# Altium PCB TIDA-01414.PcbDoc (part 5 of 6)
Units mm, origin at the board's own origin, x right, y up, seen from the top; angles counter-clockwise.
Board outline 400 x 135 mm, 4 copper layers (Top Copper, Copper Layer 2, Copper Layer 3, Bottom Copper), stack 1.567 mm thick; 835 components, 519 nets, 2420 pads, 2045 vias.
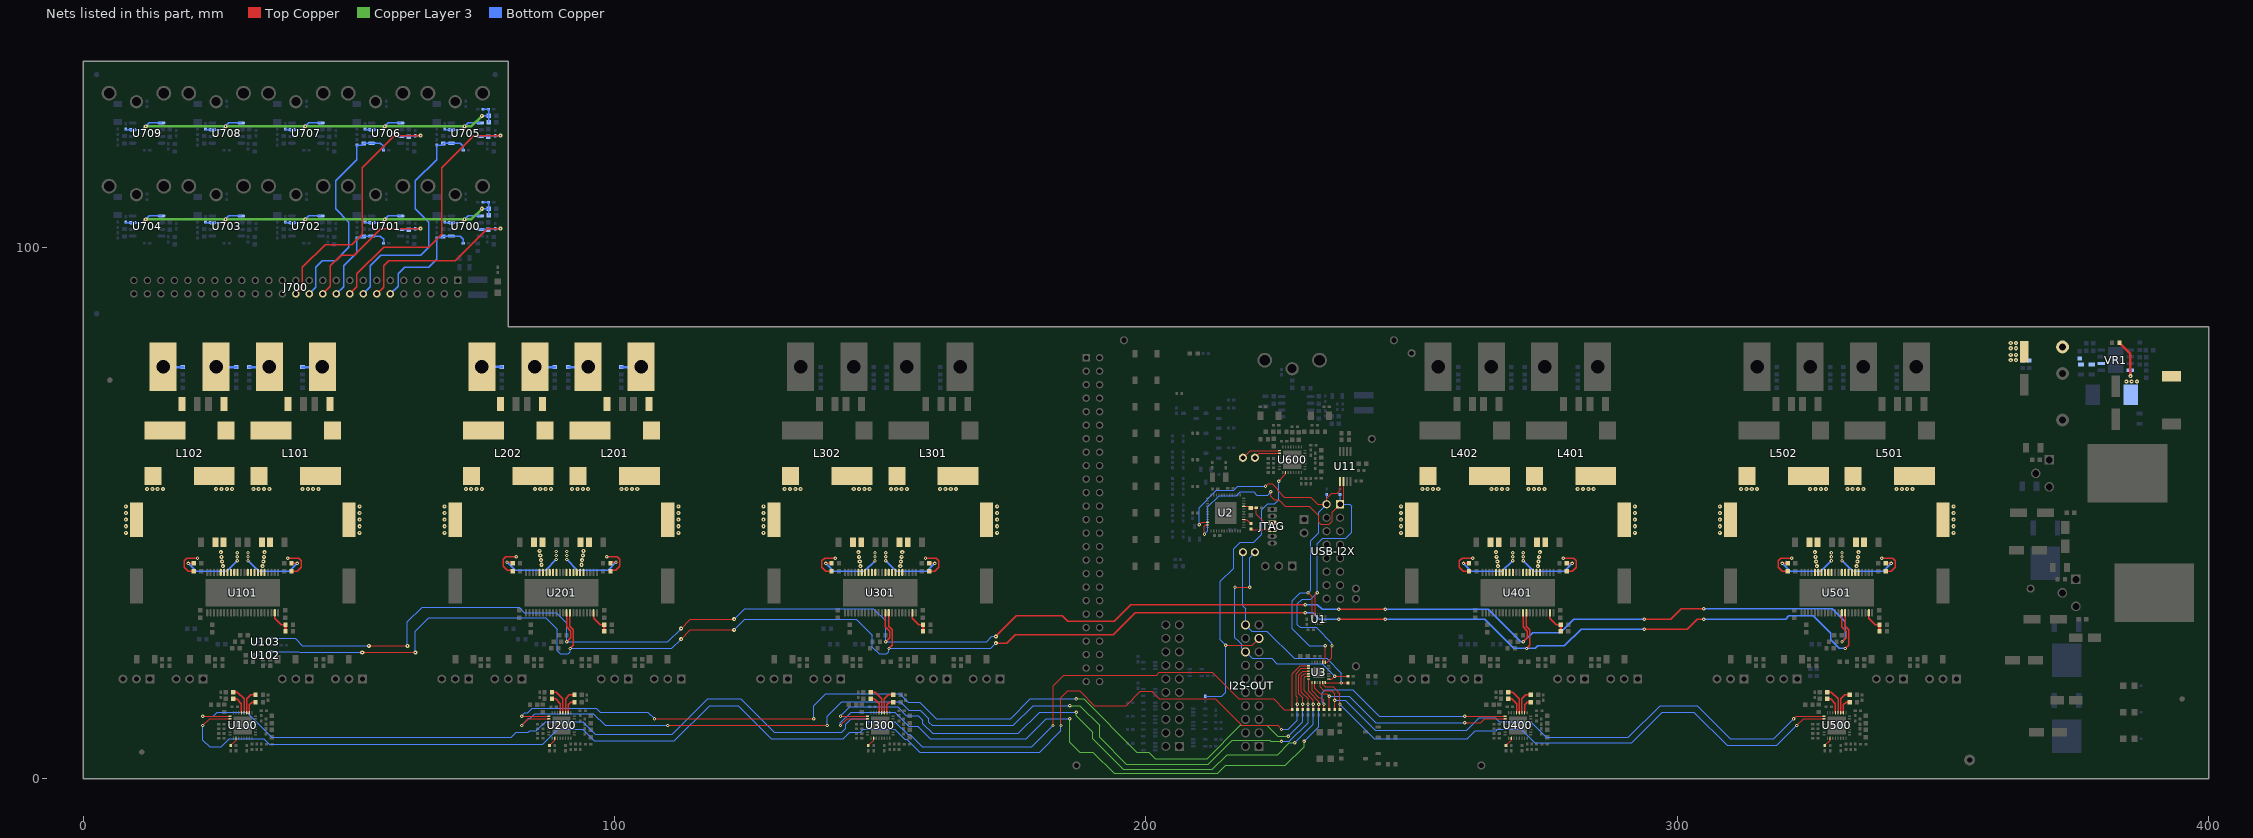
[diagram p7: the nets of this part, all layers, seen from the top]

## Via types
v1: diameter 0.635, hole 0.254, Top Copper to Bottom Copper, tented both sides, 1429 vias
v2: diameter 0.762, hole 0.254, Top Copper to Bottom Copper, tented both sides, 311 vias
v3: diameter 0.5, hole 0.2, Top Copper to Bottom Copper, 150 vias
v4: diameter 0.5, hole 0.2, Top Copper to Bottom Copper, tented both sides, 124 vias
v5: diameter 0.508, hole 0.254, Top Copper to Bottom Copper, tented both sides, 21 vias
v6: diameter 6.5, hole 4.5, Top Copper to Bottom Copper, tented both sides, 9 vias
v7: diameter 0.889, hole 0.254, Top Copper to Bottom Copper, tented both sides, 1 vias

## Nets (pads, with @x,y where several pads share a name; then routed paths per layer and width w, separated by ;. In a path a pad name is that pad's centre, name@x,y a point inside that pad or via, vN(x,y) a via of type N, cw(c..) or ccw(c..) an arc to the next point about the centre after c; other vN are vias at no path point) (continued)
OSC-IOM: U102.4 U201.14 U301.14 U401.14 U501.14 | length 355
  Top Copper w0.2: v2(52.5,23.75) v2(62.5,23.75) ; v2(112.5,26.25) 114.25,28 v2(122.5,28)
  Top Copper w0.25: U201.14@91.588,31.3 91.588,28.663 92.25,28 92.25,25.125 v1(91.625,24.5) ; U301.14@151.587,31.3 151.587,28.663 152.25,28 152.25,25.125 v1(151.625,24.5) ; v2(171.75,25.5) 173.75,25.5 175.375,27.125 193.875,27.125 198,31.25 v1(230,31.25) ; v1(236.25,30) v1(245,30) ; U401.14@271.588,31.3 271.588,28.663 272.25,28 272.25,25.125 v1(271.625,24.5) ; v1(293.75,28.125) 301.875,28.125 303.75,30 v1(305,30) ; U501.14@331.588,31.2 331.588,28.663 332.25,28 332.25,25.125 v1(331.625,24.5)
  Bottom Copper w0.2: U102.4@35.375,23.9 40.65,23.9 40.8,23.75 v2(52.5,23.75) ; v2(62.5,23.75) 62.5,27.75 65,30.25 87,30.25 89.179,28.071 89.179,24.071 89.75,23.5 91.25,23.5 91.625,23.875 v1(91.625,24.5) 110.75,24.5 v2(112.5,26.25) ; v2(122.5,28) 124.5,30 145.5,30 148.5,27 148.5,24.75 149.75,23.5 151.25,23.5 151.625,23.875 v1(151.625,24.5) 170.75,24.5 v2(171.75,25.5)
  Bottom Copper w0.25: v1(230,31.25) 231.375,31.25 232.625,30 v1(236.25,30) ; v1(245,30) 263.75,30 269.25,24.5 v1(271.625,24.5) 273.25,24.5 273.75,25 278.75,25 281.875,28.125 v1(293.75,28.125) ; v1(305,30) 320.375,30 321,30.625 325.625,30.625 328.875,27.375 328.875,26.125 330.5,24.5 v1(331.625,24.5)
OSC-IOP: U103.4 U201.13 U301.13 U401.13 U501.13 | length 353.6
  Top Copper w0.2: v2(53.75,25) v2(61,25) ; v2(112.5,28.25) 114.25,30 v2(122.5,30)
  Top Copper w0.25: U201.13@90.953,31.3 U201.13@90.953,31.2 90.953,28.548 91.75,27.75 91.75,26.5 v1(91,25.75) ; U301.13@150.952,31.3 U301.13@150.952,31.2 150.952,28.548 151.75,27.75 151.75,26.5 v1(151,25.75) ; v2(171.75,26.75) 175.625,30.625 184.25,30.625 185.25,29.625 194,29.625 197.125,32.75 v1(230,32.75) ; v1(236.25,31.875) v1(245,31.875) ; U401.13@270.953,31.3 U401.13@270.953,31.2 270.953,28.548 271.75,27.75 271.75,26.5 v1(271,25.75) ; v1(293.75,30) 298.75,30 300.75,32 v1(305,32) ; U501.13@330.953,31.2 330.953,28.548 331.75,27.75 331.75,26.5 v1(331,25.75)
  Bottom Copper w0.2: U103.4@35.375,26.4 39.85,26.4 41.25,25 v2(53.75,25) ; v2(61,25) 61,29.5 63.75,32.25 82,32.25 83,31.25 89,31.25 91,29.25 v1(91,25.75) 110,25.75 v2(112.5,28.25) ; v2(122.5,30) 124.5,32 148.702,32 151,29.702 v1(151,25.75) 170,25.75 171,26.75 v2(171.75,26.75)
  Bottom Copper w0.25: v1(230,32.75) 232.25,32.75 233.125,31.875 v1(236.25,31.875) ; v1(245,31.875) 264.375,31.875 270.5,25.75 v1(271,25.75) 272.75,27.5 278,27.5 280.5,30 v1(293.75,30) ; v1(305,32) 329.125,32 331.625,29.5 331.625,26.375 v1(331,25.75)
OUT1A: C120.1 L101.1 U101.27 U101.28 | length 6.4
  Top Copper w0.25: v1(38.5,41.5) 40.5,41.5 41,41 41,39.75 ; C120.1@39.2,39 40.25,39 41,39.75 ; 40.75,39.5 41,39.75
  other v2: 33.75,40 33.875,40.875 34,41.75 34.125,42.625 41.25,54.5 42.25,54.5 43.25,54.5 44.25,54.5
OUT1B: C123.1 L101.4 U101.32 | length 11.7
  Top Copper w0.25: C123.1@39.2,40.5 v1(40.25,40.5)
  Bottom Copper w0.25: v1(31,41) 33,39 38.75,39 v1(40.25,40.5)
  other v1: 31,41.75 31,42.5
  other v2: 32,54.5 33,54.5 34,54.5 35,54.5
OUT1C: C138.1 L102.1 U101.35 | length 11.7
  Top Copper w0.25: v1(19.75,40.5) C138.1@20.8,40.5
  Bottom Copper w0.25: v1(19.75,40.5) 21.25,39 27,39 v1(29,41)
  other v1: 29,41.75 29,42.5
  other v2: 25,54.5 26,54.5 27,54.5 28,54.5
OUT1D: C139.1 L102.4 U101.39 U101.40 | length 6.1
  Top Copper w0.25: C139.1@20.8,39 19.75,39 19,39.75 19,40.25 19,41 19.5,41.5 v1(21.5,41.5)
  other v2: 26.25,40 26.125,40.875 26,41.75 25.875,42.625 12,54.5 13,54.5 14,54.5 15,54.5
OUT2A: C220.1 L201.1 U201.27 U201.28 | length 6.4
  Top Copper w0.25: v1(98.5,41.75) 100.5,41.75 101,41.25 101,40 ; C220.1@99.2,39.25 100.25,39.25 101,40 ; 100.75,39.75 101,40
  other v2: 93.75,40.25 93.875,41.125 94,42 94.125,42.875 101.25,54.5 102.25,54.5 103.25,54.5 104.25,54.5
OUT2B: C223.1 L201.4 U201.32 | length 11.7
  Top Copper w0.25: C223.1@99.2,40.75 v1(100.25,40.75)
  Bottom Copper w0.25: v1(91,41.25) 93,39.25 98.75,39.25 v1(100.25,40.75)
  other v1: 91,42 91,42.75
  other v2: 92,54.5 93,54.5 94,54.5 95,54.5
OUT2C: C238.1 L202.1 U201.35 | length 11.7
  Top Copper w0.25: v1(79.75,40.75) C238.1@80.8,40.75
  Bottom Copper w0.25: v1(79.75,40.75) 81.25,39.25 87,39.25 v1(89,41.25)
  other v1: 89,42 89,42.75
  other v2: 85,54.5 86,54.5 87,54.5 88,54.5
OUT2D: C239.1 L202.4 U201.39 U201.40 | length 6.1
  Top Copper w0.25: C239.1@80.8,39.25 79.75,39.25 79,40 79,40.5 79,41.25 79.5,41.75 v1(81.5,41.75)
  other v2: 86.25,40.25 86.125,41.125 86,42 85.875,42.875 72,54.5 73,54.5 74,54.5 75,54.5
OUT3A: C320.1 L301.1 U301.27 U301.28 | length 6.4
  Top Copper w0.25: v1(158.5,41.5) 160.5,41.5 161,41 161,39.75 ; C320.1@159.2,39 160.25,39 161,39.75 ; 160.75,39.5 161,39.75
  other v2: 153.75,40 153.875,40.875 154,41.75 154.125,42.625 161.25,54.5 162.25,54.5 163.25,54.5 164.25,54.5
OUT3B: C323.1 L301.4 U301.32 | length 11.7
  Top Copper w0.25: C323.1@159.2,40.5 v1(160.25,40.5)
  Bottom Copper w0.25: v1(151,41) 153,39 158.75,39 v1(160.25,40.5)
  other v1: 151,41.75 151,42.5
  other v2: 152,54.5 153,54.5 154,54.5 155,54.5
OUT3C: C338.1 L302.1 U301.35 | length 11.7
  Top Copper w0.25: v1(139.75,40.5) C338.1@140.8,40.5
  Bottom Copper w0.25: v1(139.75,40.5) 141.25,39 147,39 v1(149,41)
  other v1: 149,41.75 149,42.5
  other v2: 145,54.5 146,54.5 147,54.5 148,54.5
OUT3D: C339.1 L302.4 U301.39 U301.40 | length 6.1
  Top Copper w0.25: C339.1@140.8,39 139.75,39 139,39.75 139,40.25 139,41 139.5,41.5 v1(141.5,41.5)
  other v2: 146.25,40 146.125,40.875 146,41.75 145.875,42.625 132,54.5 133,54.5 134,54.5 135,54.5
OUT4A: C420.1 L401.1 U401.27 U401.28 | length 6.4
  Top Copper w0.25: v1(278.5,41.5) 280.5,41.5 281,41 281,39.75 ; C420.1@279.2,39 280.25,39 281,39.75 ; 280.75,39.5 281,39.75
  other v2: 273.75,40 273.875,40.875 274,41.75 274.125,42.625 281.25,54.5 282.25,54.5 283.25,54.5 284.25,54.5
OUT4B: C423.1 L401.4 U401.32 | length 11.7
  Top Copper w0.25: C423.1@279.2,40.5 v1(280.25,40.5)
  Bottom Copper w0.25: v1(271,41) 273,39 278.75,39 v1(280.25,40.5)
  other v1: 271,41.75 271,42.5
  other v2: 272,54.5 273,54.5 274,54.5 275,54.5
OUT4C: C438.1 L402.1 U401.35 | length 11.7
  Top Copper w0.25: v1(259.75,40.5) C438.1@260.8,40.5
  Bottom Copper w0.25: v1(259.75,40.5) 261.25,39 267,39 v1(269,41)
  other v1: 269,41.75 269,42.5
  other v2: 265,54.5 266,54.5 267,54.5 268,54.5
OUT4D: C439.1 L402.4 U401.39 U401.40 | length 6.1
  Top Copper w0.25: C439.1@260.8,39 259.75,39 259,39.75 259,40.25 259,41 259.5,41.5 v1(261.5,41.5)
  other v2: 266.25,40 266.125,40.875 266,41.75 265.875,42.625 252,54.5 253,54.5 254,54.5 255,54.5
OUT5A: C520.1 L501.1 U501.27 U501.28 | length 6.4
  Top Copper w0.25: v1(338.5,41.5) 340.5,41.5 341,41 341,39.75 ; C520.1@339.2,39 340.25,39 341,39.75 ; 340.75,39.5 341,39.75
  other v2: 333.75,40 333.875,40.875 334,41.75 334.125,42.625 341.25,54.5 342.25,54.5 343.25,54.5 344.25,54.5
OUT5B: C523.1 L501.4 U501.32 | length 11.7
  Top Copper w0.25: C523.1@339.2,40.5 v1(340.25,40.5)
  Bottom Copper w0.25: v1(331,41) 333,39 338.75,39 v1(340.25,40.5)
  other v1: 331,41.75 331,42.5
  other v2: 332,54.5 333,54.5 334,54.5 335,54.5
OUT5C: C538.1 L502.1 U501.35 | length 11.7
  Top Copper w0.25: v1(319.75,40.5) C538.1@320.8,40.5
  Bottom Copper w0.25: v1(319.75,40.5) 321.25,39 327,39 v1(329,41)
  other v1: 329,41.75 329,42.5
  other v2: 325,54.5 326,54.5 327,54.5 328,54.5
OUT5D: C539.1 L502.4 U501.39 U501.40 | length 6.1
  Top Copper w0.25: C539.1@320.8,39 319.75,39 319,39.75 319,40.25 319,41 319.5,41.5 v1(321.5,41.5)
  other v2: 326.25,40 326.125,40.875 326,41.75 325.875,42.625 312,54.5 313,54.5 314,54.5 315,54.5
OUTLN1: R103.1 U100.11 | length 4.6
  Top Copper w0.25: U100.11@30.75,12.4 30.75,15 31.5,15.75 R103.1@32.425,15.75
OUTLN2: R203.1 U200.11 | length 4.6
  Top Copper w0.25: U200.11@90.75,12.4 90.75,15 91.5,15.75 R203.1@92.425,15.75
OUTLN3: R303.1 U300.11 | length 4.6
  Top Copper w0.25: U300.11@150.75,12.4 150.75,15 151.5,15.75 R303.1@152.425,15.75
OUTLN4: R403.1 U400.11 | length 4.6
  Top Copper w0.25: U400.11@270.75,12.4 270.75,15 271.5,15.75 R403.1@272.425,15.75
OUTLN5: R503.1 U500.11 | length 4.6
  Top Copper w0.25: U500.11@330.75,12.4 330.75,15 331.5,15.75 R503.1@332.425,15.75
OUTLP1: R101.1 U100.10 | length 2.9
  Top Copper w0.25: U100.10@31.25,12.4 31.25,13.875 31.75,14.375 R101.1@32.425,14.375
OUTLP2: R201.1 U200.10 | length 2.9
  Top Copper w0.25: U200.10@91.25,12.4 91.25,13.875 91.75,14.375 R201.1@92.425,14.375
OUTLP3: R301.1 U300.10 | length 2.9
  Top Copper w0.25: U300.10@151.25,12.4 151.25,13.875 151.75,14.375 R301.1@152.425,14.375
OUTLP4: R401.1 U400.10 | length 2.9
  Top Copper w0.25: U400.10@271.25,12.4 271.25,13.875 271.75,14.375 R401.1@272.425,14.375
OUTLP5: R501.1 U500.10 | length 2.9
  Top Copper w0.25: U500.10@331.25,12.4 331.25,13.875 331.75,14.375 R501.1@332.425,14.375
OUTRN1: R105.1 U100.12 | length 5.2
  Top Copper w0.25: R105.1@28.2,16.25 29,16.25 30.25,15 U100.12@30.25,12.4
OUTRN2: R205.1 U200.12 | length 5.2
  Top Copper w0.25: R205.1@88.2,16.25 89,16.25 90.25,15 U200.12@90.25,12.4
OUTRN3: R305.1 U300.12 | length 5.2
  Top Copper w0.25: R305.1@148.2,16.25 149,16.25 150.25,15 U300.12@150.25,12.4
OUTRN4: R405.1 U400.12 | length 5.2
  Top Copper w0.25: R405.1@268.2,16.25 269,16.25 270.25,15 U400.12@270.25,12.4
OUTRN5: R505.1 U500.12 | length 5.2
  Top Copper w0.25: R505.1@328.2,16.25 329,16.25 330.25,15 U500.12@330.25,12.4
OUTRP1: R107.1 U100.13 | length 3.6
  Top Copper w0.25: R107.1@28.2,15 28.875,15 29.75,14.125 U100.13@29.75,12.4
OUTRP2: R207.1 U200.13 | length 3.6
  Top Copper w0.25: R207.1@88.2,15 88.875,15 89.75,14.125 U200.13@89.75,12.4
OUTRP3: R307.1 U300.13 | length 3.6
  Top Copper w0.25: R307.1@148.2,15 148.875,15 149.75,14.125 U300.13@149.75,12.4
OUTRP4: R407.1 U400.13 | length 3.6
  Top Copper w0.25: R407.1@268.2,15 268.875,15 269.75,14.125 U400.13@269.75,12.4
OUTRP5: R507.1 U500.13 | length 3.6
  Top Copper w0.25: R507.1@328.2,15 328.875,15 329.75,14.125 U500.13@329.75,12.4
PVDD: C5.1 C6.2 C8.1 C9.1 C10.1 C100.1 C102.2 C103.2 C111.1 C113.2 C114.2 C200.1 C202.2 C203.2 C211.1 C213.2 C214.2 C300.1 C302.2 C303.2 C311.1 C313.2 C314.2 C400.1 C402.2 C403.2 C411.1 C413.2 C414.2 C500.1 C502.2 C503.2 C511.1 C513.2 C514.2 PWR-IN.1 R35.2 U101.29 U101.30 U101.31 U101.36 U101.37 U101.38 U201.29 U201.30 U201.31 U201.36 U201.37 U201.38 U301.29 U301.30 U301.31 U301.36 U301.37 U301.38 U401.29 U401.30 U401.31 U401.36 U401.37 U401.38 U501.29 U501.30 U501.31 U501.36 U501.37 U501.38 VR1.2
  other v2: 8,46.25 52,46.25 68,46.25 112,46.25 128,46.25 172,46.25 248,46.25 292,46.25 308,46.25 352,46.25 8,47.5 52,47.5 68,47.5 112,47.5 128,47.5 172,47.5 248,47.5 292,47.5 308,47.5 352,47.5 8,48.75 52,48.75 68,48.75 112,48.75 128,48.75 172,48.75 248,48.75 292,48.75 308,48.75 352,48.75 8,50 52,50 68,50 112,50 128,50 172,50 248,50 292,50 308,50 352,50 8,51.25 52,51.25 68,51.25 112,51.25 128,51.25 172,51.25 248,51.25 292,51.25 308,51.25 352,51.25 362.75,78.75 363.75,78.75 362.75,79.75 363.75,79.75 362.75,81 363.75,81 362.75,82 363.75,82
SBWTCK: R43.1 U2.40 | length 1.7
  Top Copper w0.2: U2.40@218.4,48.75 219,48.75 R43.1@219.75,48
SBWTDIO: C52.2 JTAG.3 R41.1 U2.45 | length 7.5
  Top Copper w0.2: U2.45@218.4,51.25 219.45,51.25 C52.2@219.75,50.95 C52.2@219.8,51 ; C52.2@219.75,51 C52.2@219.8,51 ; JTAG.3@223.75,48.135 222.365,48.135 220.75,49.75 R41.1@220.75,51 C52.2@219.8,51
SCK1: R81.1 U100.26 | length 1.8
  Top Copper w0.2: R81.1@27.75,6.25 28.75,7.25 U100.26@28.75,7.6
SCK2: R82.1 U200.26 | length 1.8
  Top Copper w0.2: R82.1@87.75,6.25 88.75,7.25 U200.26@88.75,7.6
SCK3: R83.1 U300.26 | length 1.8
  Top Copper w0.2: R83.1@147.75,6.25 148.75,7.25 U300.26@148.75,7.6
SCK4: R84.1 U400.26 | length 1.8
  Top Copper w0.2: R84.1@267.75,6.25 268.75,7.25 U400.26@268.75,7.6
SCK5: R85.1 U500.26 | length 1.8
  Top Copper w0.2: R85.1@327.75,6.25 328.75,7.25 U500.26@328.75,7.6
SCK6: I2S-OUT.17 R86.1 U600.26 | length 60.1
  Top Copper w0.2: v1(215,25.125) 220.005,25.125 I2S-OUT.17@221.27,26.39 ; v1(225,56) 226.25,57.25 U600.26@226.25,57.6
  Bottom Copper w0.2: R86.1@211.125,15.5 214.25,15.5 215,16.25 v1(215,25.125) 214,26.125 214,37.125 216.5,39.625 216.5,43.25 217.75,44.5 220.25,44.5 221.75,46 221.75,50.625 222.875,51.75 224.25,51.75 225,52.5 v1(225,56)
SCL: R12.2 U1.12 U2.23 U3.19 U11.6 USB-I2X.1 | length 96.3
  Top Copper w0.2: v1(211,46) 211,47.5 211.25,47.75 U2.23@211.6,47.75 ; v1(223.5,54) 223.5,53.125 224.125,52.5 225,52.5 225.25,52.25 226.25,51.25 230.75,51.25 232.5,49.5 232.5,48.25 232.875,47.875 234.5,47.875 235.055,48.43 235.055,50.175 USB-I2X.1@236.52,51.64 USB-I2X.1@236.75,51.64 ; U1.12@231.9,30.8 231.9,34.65 v1(232.25,35) ; U3.19@233.75,21.9 234.15,21.9 235,22.75 v1(235,25) ; USB-I2X.1@236.75,51.5 237.175,51.925 U11.6@237.175,55.9
  Bottom Copper w0.2: v1(211,46) 211.625,46.625 211.625,51.125 213.75,53.25 217,53.25 217.75,54 220.25,54 220.875,53.375 222.875,53.375 v1(223.5,54) ; v1(235,25) 235,25.5 232,28.5 229,28.5 228.5,29 228.5,32.875 229.375,33.75 231,33.75 v1(232.25,35) 232.25,44.25 233.25,45.25 237.625,45.25 238.75,46.375 238.75,51.25 238.36,51.64 USB-I2X.1@236.52,51.64 236.52,53.48 R12.2@236.5,53.5
SCL1: R15.1 U3.2 U100.18 | length 252.8
  Top Copper w0.2: v1(22.5,10) 23.75,11.25 U100.18@27.6,11.25 ; v1(184,10) 184,15.25 185.25,16.5 187.5,16.5 190.25,13.75 196.25,13.75 198.937,16.437 201.063,16.437 202.5,15 213,15 218,10 224.75,10 v1(225.5,9.25) ; R15.1@228.5,13 v1(228.5,14) 228.5,15.25 228.25,15.5 228.25,19.75 229.25,20.75 U3.2@230.6,20.75
  Bottom Copper w0.2: v1(22.5,10) 22.5,7.25 23.75,6 26,6 27.5,7.5 34,7.5 35,6.5 86.5,6.5 89.25,9.25 94,9.25 96.125,7.125 111.25,7.125 117.875,13.75 123.25,13.75 129.5,7.5 143,7.5 144.25,8.75 146.25,8.75 146.75,9.25 152.75,9.25 154.625,7.375 155,7.375 157.375,5 180,5 184,9 v1(184,10) ; v1(225.5,9.25) 226.75,9.25 228.5,11 v1(228.5,14)
SCL2: R11.1 U3.4 U200.18 | length 183.3
  Top Copper w0.2: v1(82.5,10) 83.75,11.25 U200.18@87.6,11.25 ; v1(110,10) v1(140,10) ; R11.1@230.5,13 v1(230.5,14) 230.5,15 229.25,16.25 229.25,19.25 229.75,19.75 U3.4@230.6,19.75
  Copper Layer 3 w0.2: v1(185.625,13.75) 187.5,13.75 191.25,10 191.25,7.75 196.25,2.75 211.75,2.75 216.25,7.25 223.25,7.25 223.5,7 v1(225.5,7)
  Bottom Copper w0.2: v1(82.5,10) 83.875,11.375 84.125,11.375 85,12.25 96,12.25 98.25,10 v1(110,10) ; v1(140,10) 140,11.75 142.75,14.5 153.75,14.5 155.375,12.875 157.5,12.875 159.125,11.25 159.125,10.625 159.75,10 175,10 178.75,13.75 v1(185.625,13.75) ; v1(225.5,7) 227,7 230.5,10.5 v1(230.5,14)
SCL3: R9.1 U3.6 U300.18 | length 122.4
  Top Copper w0.2: v1(142.5,10) 143.75,11.25 U300.18@147.6,11.25 ; U3.6@230.6,18.75 230.6,16.4 232.5,14.5 v1(232.5,14) R9.1@232.5,13
  Copper Layer 3 w0.2: v1(185.625,11.25) 185.625,6.875 187.5,5 190,5 194,1 213.5,1 215,2.5 226.25,2.5 229.75,6 v1(229.75,7)
  Bottom Copper w0.2: v1(142.5,10) 142.5,10.5 144.5,12.5 152.75,12.5 155.375,9.875 157,9.875 159.375,7.5 177.5,7.5 181.25,11.25 v1(185.625,11.25) ; v1(229.75,7) 232.5,9.75 v1(232.5,14)
SCL4: R7.1 U3.8 U400.18 | length 42.5
  Top Copper w0.2: U3.8@231.75,18.1 231.75,17 232.75,16 234,16 v1(234.5,15.5) R7.1@234.5,13 ; v1(260,10.5) 263,10.5 263.75,11.25 U400.18@267.6,11.25
  Bottom Copper w0.2: v1(234.5,15.5) 238.25,15.5 243.25,10.5 v1(260,10.5)
SCL5: R5.1 U3.11 U500.18 | length 109.9
  Top Copper w0.2: U3.11@233.25,18.1 233.25,17.75 233.75,17.25 235.25,17.25 236.5,16 v1(236.5,14) R5.1@236.5,13 ; v1(322.5,10) 323.75,11.25 U500.18@327.6,11.25
  Bottom Copper w0.2: v1(236.5,14) 243,7.5 260.5,7.5 262,9 265.875,9 266.125,9.25 270.625,9.25 273.125,6.75 291.375,6.75 297.125,12.5 303.125,12.5 309.375,6.25 318.75,6.25 v1(322.5,10)
SCL6: I2S-OUT.16 J601.1 R3.1 U3.13 | length 45.2
  Top Copper w0.2: v1(216.75,36) v1(219.5,36) ; U3.13@234.4,18.75 235,18.75 v1(235.5,19.25) R3.1@238,19.25
  Bottom Copper w0.2: v1(216.75,36) 216.75,26.5 217.25,26 218,25.25 218,24.58 I2S-OUT.16@218.73,23.85 219.955,22.625 223.625,22.625 224.625,21.625 233.125,21.625 v1(235.5,19.25) ; v1(219.5,36) 219.5,41.61 J601.1@220.5,42.61
SCL7: J601.2 U600.18 | length 5
  Top Copper w0.2: J601.2@220.5,60.39 221.36,61.25 U600.18@225.1,61.25
SDA: R13.2 U1.13 U2.22 U3.20 U11.5 USB-I2X.2 | length 83
  Top Copper w0.2: v1(210,47.75) 210.5,48.25 U2.22@211.6,48.25 ; v1(222.5,55) 223,55.5 223.75,55.5 224.75,54.5 224.75,54.25 226,53 231,53 232.36,51.64 USB-I2X.2@233.98,51.64 233.98,52.73 235,53.75 236,53.75 236.525,54.275 U11.5@236.525,55.9 ; v1(230.5,35) 231.3,34.2 U1.13@231.3,30.6 ; U3.20@233.25,21.9 233.25,22.25 233.75,22.75 v1(233.75,25)
  Bottom Copper w0.2: v1(210,47.75) 210,51 213.25,54.25 216.5,54.25 217.25,55 v1(222.5,55) ; v1(233.75,25) 230.75,25 227.5,28.25 227.5,33.5 229,35 v1(230.5,35) 231,35.5 231,44.75 232.5,46.25 232.5,50.16 USB-I2X.2@233.98,51.64 233.98,53.48 R13.2@234,53.5
SDA1: R16.1 U3.1 U100.17 | length 247.2
  Top Copper w0.2: v1(22.5,11.75) U100.17@27.6,11.75 ; v1(182.5,10) 182.5,17.5 184.5,19.5 202,19.5 202.5,20 212.5,20 217.5,15 224,15 226,13 R16.1@227.5,13 227.5,19.75 229,21.25 U3.1@230.6,21.25
  Bottom Copper w0.2: v1(22.5,11.75) 24.5,11.75 25.25,12.5 30.75,12.5 35.5,7.75 80.5,7.75 81.5,8.75 83.75,8.75 84,9 85.25,9 85.5,9.25 87,10.75 94,10.75 96.375,8.375 110.875,8.375 117.5,15 123.75,15 130,8.75 142.75,8.75 143.5,9.5 143.5,10.25 144.5,11.25 147.25,11.25 147.75,10.75 152.75,10.75 155.125,8.375 155.5,8.375 157.875,6 178.5,6 v1(182.5,10)
SDA2: R14.1 U3.3 U200.17 | length 181.9
  Top Copper w0.2: v1(82.5,11.75) U200.17@87.6,11.75 ; v1(107.5,11.25) v1(137.5,11.25) ; R14.1@229.5,13 v1(229.5,14) 229.5,15.25 228.75,16 228.75,19.5 229.5,20.25 U3.3@230.6,20.25
  Copper Layer 3 w0.2: v1(186.875,15) 188.25,15 198.25,5 200.5,5 201.75,3.75 211.5,3.75 217.75,10 222.75,10 224.75,8 v1(226.75,8)
  Bottom Copper w0.2: v1(82.5,11.75) 83.125,12.375 83.625,12.375 84.5,13.25 96.5,13.25 97.25,12.5 106.25,12.5 v1(107.5,11.25) ; v1(137.5,11.25) 137.5,13.75 139.75,16 153.625,16 155.25,14.375 157.375,14.375 160.5,11.25 174.5,11.25 178.25,15 v1(186.875,15) ; v1(226.75,8) 229.5,10.75 v1(229.5,14)
SDA3: R10.1 U3.5 U300.17 | length 119.4
  Top Copper w0.2: v1(142.5,11.75) U300.17@147.6,11.75 ; U3.5@230.6,19.25 230,19.25 229.75,19 229.75,16.5 231.5,14.75 v1(231.5,14) R10.1@231.5,13
  Copper Layer 3 w0.2: v1(186.875,12.5) 186.875,11.875 190,8.75 190,7.5 195.75,1.75 212.5,1.75 215.25,4.5 224.75,4.5 227,6.75 v1(228,6.75)
  Bottom Copper w0.2: v1(142.5,11.75) 144.25,13.5 153.25,13.5 154.875,11.875 157.125,11.875 158,11 158,10.375 159.875,8.5 176,8.5 180,12.5 v1(186.875,12.5) ; v1(228,6.75) 231.5,10.25 v1(231.5,14)
SDA4: R8.1 U3.7 U400.17 | length 45.4
  Top Copper w0.2: U3.7@231.25,18.1 231.25,16.5 232.5,15.25 233,15.25 233.5,14.75 v1(233.5,14) R8.1@233.5,13 ; v1(260,11.75) U400.17@267.6,11.75
  Bottom Copper w0.2: v1(233.5,14) 233.125,14.375 233.125,16.125 233.75,16.75 238.875,16.75 243.875,11.75 v1(260,11.75)
SDA5: R6.1 U3.10 U500.17 | length 110.9
  Top Copper w0.2: U3.10@232.75,18.1 232.75,17.25 233.5,16.5 235,16.5 235.5,16 v1(235.5,14.75) R6.1@235.5,13 ; v1(321.875,11.25) 322.375,11.75 U500.17@327.6,11.75
  Bottom Copper w0.2: v1(235.5,14.75) 237.5,14.75 243.125,9.125 260.375,9.125 262.75,11.5 265.75,11.5 266.5,10.75 272.375,10.75 275.375,7.75 290.75,7.75 296.75,13.75 303.75,13.75 310,7.5 318.125,7.5 v1(321.875,11.25)
SDA6: I2S-OUT.20 J600.1 R4.1 U3.12 | length 41.9
  Top Copper w0.2: U3.12@233.75,18.1 233.75,18 v1(236.75,18) R4.1@238,18
  Bottom Copper w0.2: J600.1@218.25,42.61 218.25,32.5 218.75,32 218.75,28.95 I2S-OUT.20@218.73,28.93 219.91,27.75 222.75,27.75 227.875,22.625 234,22.625 236.75,19.875 v1(236.75,18)
SDA7: J600.2 U600.17 | length 7.4
  Top Copper w0.2: J600.2@218.25,60.39 219.61,61.75 U600.17@225.1,61.75
SL+: C727.2 J700.12 R700.1 R710.1 U700.1 | length 22.9
  Bottom Copper w0.25: J700.12@57.78,91.23 59.25,92.7 59.25,95 60.5,96.25 65,96.25 66.5,97.75 R700.1@66.5,101.75 67.45,101.75 C727.2@67.75,102.05 67.795,102.095 U700.1@69.275,102.095 70.905,102.095 71.5,101.5 R710.1@71.5,100.75
SL-: C737.2 J700.14 R715.1 U700.7 | length 34.6
  Top Copper w0.25: J700.14@55.24,91.23 56.5,92.49 56.5,96.5 57.5,97.5 70,97.5 76,103.5 v2(78.5,103.5)
  Bottom Copper w0.25: U700.7@74.725,103.365 76.185,103.365 C737.2@76.25,103.3 76.45,103.5 R715.1@77.5,103.5 v2(78.5,103.5)
SR+: C742.2 J700.16 R720.1 R730.1 U705.1 | length 46.3
  Bottom Copper w0.25: J700.16@52.7,91.23 54,92.53 54,96.5 56,98.5 63.5,98.5 65,100 65,104.75 62.5,107.25 62.5,112.5 66.5,116.5 R720.1@66.5,119.25 67.45,119.25 67.795,119.595 70.905,119.595 71.5,119 R730.1@71.5,118.25
SR-: C752.2 J700.18 R735.1 U705.7 | length 53.3
  Top Copper w0.25: J700.18@50.16,91.23 51.5,92.57 51.5,95 56.5,100 65,100 67.5,102.5 67.5,115 73.5,121 v2(78.5,121)
  Bottom Copper w0.25: U705.7@74.725,120.865 76.185,120.865 C752.2@76.25,120.8 76.45,121 v2(78.5,121)
SURROUNDLEFT+: C115.1 C116.1 L101.2 SL+.1 | length 3.8
  Bottom Copper w0.5: C116.1@41.25,77.45 44.95,77.45 SL+.1@45,77.5
SURROUNDLEFT-: C126.1 C127.1 L101.3 SL-.1 | length 3.8
  Bottom Copper w0.5: C127.1@31.25,77.45 34.95,77.45 SL-.1@35,77.5
SURROUNDRIGHT+: C135.1 C136.1 L102.2 SR+.1 | length 3.8
  Bottom Copper w0.5: SR+.1@25,77.5 25.05,77.45 C136.1@28.75,77.45
SURROUNDRIGHT-: C140.1 C141.1 L102.3 SR-.1 | length 3.8
  Bottom Copper w0.5: SR-.1@15,77.5 15.05,77.45 C141.1@18.75,77.45
SW-VR1: C1.2 D12.1 L1.1 VR1.8 | length 8.2
  Top Copper w0.5: C1.2@383.2,82 385.25,79.95 v2(385.25,75.75)
  Bottom Copper w0.5: VR1.8@385.225,76.845 385.25,76.82 v2(385.25,75.75)
  other v2: 384.5,74.75 385.5,74.75 386.5,74.75
TCK: JTAG.4 R43.2 | length 4.1
  Top Copper w0.2: R43.2@219.75,47 219.885,46.865 JTAG.4@223.75,46.865
UML+: C728.2 J700.20 R701.1 R711.1 U701.1 | length 18.3
  Bottom Copper w0.25: J700.20@47.62,91.23 49,92.61 49,96.5 51.5,99 R701.1@51.5,101.75 52.45,101.75 52.795,102.095 U701.1@54.275,102.095 55.905,102.095 56.5,101.5 R711.1@56.5,100.75
UML-: C738.2 J700.22 R716.1 U701.7 | length 29.6
  Top Copper w0.25: J700.22@45.08,91.23 46.5,92.65 46.5,96.5 48.5,98.5 51,98.5 56,103.5 v2(63.5,103.5)
  Bottom Copper w0.25: U701.7@59.725,103.365 61.185,103.365 C738.2@61.25,103.3 61.45,103.5 R716.1@62.5,103.5 v2(63.5,103.5)
UMR+: C743.2 J700.24 R721.1 R731.1 U706.1 | length 41.4
  Bottom Copper w0.25: J700.24@42.54,91.23 43.75,92.44 43.75,96.25 45,97.5 47.5,97.5 50,100 50,104.75 47.5,107.25 47.5,112.5 51.5,116.5 R721.1@51.5,119.25 52.45,119.25 52.795,119.595 55.905,119.595 56.5,119 R731.1@56.5,118.25
UMR-: C753.2 J700.26 R736.1 U706.7 | length 49.2
  Top Copper w0.25: J700.26@40,91.23 41.25,92.48 41.25,96.25 45.5,100.5 50.5,100.5 52.5,102.5 52.5,115 58.5,121 v2(63.5,121)
  Bottom Copper w0.25: U706.7@59.725,120.865 61.185,120.865 C753.2@61.25,120.8 61.45,121 v2(63.5,121)
UPL+: C215.1 C216.1 L201.2 UPL+.1 | length 3.8
  Bottom Copper w0.5: C216.1@101.25,77.45 104.95,77.45 UPL+.1@105,77.5
UPL-: C226.1 C227.1 L201.3 UPL-.1 | length 3.8
  Bottom Copper w0.5: C227.1@91.25,77.45 94.95,77.45 UPL-.1@95,77.5
UPR+: C235.1 C236.1 L202.2 UPR+.1 | length 3.8
  Bottom Copper w0.5: UPR+.1@85,77.5 85.05,77.45 C236.1@88.75,77.45
UPR-: C240.1 C241.1 L202.3 UPR-.1 | length 3.8
  Bottom Copper w0.5: UPR-.1@75,77.5 78.7,77.5 C241.1@78.75,77.45
VDD1: C112.1 L100.2 U101.21 | length 4.8
  Top Copper w0.25: U101.21@36.033,31.3 U101.21@36.033,31.2 36.033,30.218 37.25,29 C112.1@38,29
  Top Copper w0.5: C112.1@38,29 C112.1@38.05,29 L100.2@38.05,27.8
VDD2: C212.1 L200.2 U201.21 | length 4.8
  Top Copper w0.25: U201.21@96.033,31.3 U201.21@96.033,31.2 96.033,30.218 97.25,29 C212.1@98,29
  Top Copper w0.5: C212.1@98,29 C212.1@98.05,29 L200.2@98.05,27.8
VDD3: C312.1 L300.2 U301.21 | length 4.8
  Top Copper w0.25: U301.21@156.032,31.3 U301.21@156.032,31.2 156.032,30.218 157.25,29 C312.1@158,29
  Top Copper w0.5: C312.1@158,29 C312.1@158.05,29 L300.2@158.05,27.8
VDD4: C412.1 L400.2 U401.21 | length 4.8
  Top Copper w0.25: U401.21@276.033,31.3 U401.21@276.033,31.2 276.033,30.218 277.25,29 C412.1@278,29
  Top Copper w0.5: C412.1@278,29 C412.1@278.05,29 L400.2@278.05,27.8
VDD5: C512.1 L500.2 U501.21 | length 4.8
  Top Copper w0.25: U501.21@336.033,31.3 U501.21@336.033,31.2 336.033,30.218 337.25,29 C512.1@338,29
  Top Copper w0.5: C512.1@338,29 C512.1@338.05,29 L500.2@338.05,27.8
VMID1: C713.2 C714.2 C732.2 C733.2 C734.2 C735.2 C736.2 R740.2 R742.1 U700.3 U700.5 U701.3 U701.5 U702.3 U702.5 U703.3 U703.5 U704.3 U704.5 | length 105.4
  Copper Layer 3 w0.5: v2(11.75,105.25) v2(71.75,105.25) 73,105.25 v2(75,107.25)
  Bottom Copper w0.25: C736.2@8,104.75 8.115,104.635 U704.3@9.275,104.635 11.135,104.635 v2(11.75,105.25) 12.405,105.905 U704.5@14.725,105.905 ; C735.2@23,104.75 23.115,104.635 26.135,104.635 v2(26.75,105.25) 27.405,105.905 U703.5@29.725,105.905 ; C734.2@38,104.75 38.115,104.635 U702.3@39.275,104.635 41.135,104.635 v2(41.75,105.25) 42.405,105.905 U702.5@44.725,105.905 ; C733.2@53,104.75 53.115,104.635 U701.3@54.275,104.635 56.135,104.635 v2(56.75,105.25) 57.405,105.905 U701.5@59.725,105.905 ; C732.2@68,104.75 68.115,104.635 U700.3@69.275,104.635 71.135,104.635 v2(71.75,105.25) 72.405,105.905 U700.5@74.725,105.905 ; v2(75,107.25) C713.2@76.25,107.25 ; R740.2@75.25,108.5 R742.1@76.25,108.5 76.3,108.45 C713.2@76.3,107.25 C713.2@76.25,107.25 ; C714.2@76.3,106 76.3,107.2 C713.2@76.25,107.25
VMID2: C715.2 C716.2 C747.2 C748.2 C749.2 C750.2 C751.2 R741.2 R743.1 U705.3 U705.5 U706.3 U706.5 U707.3 U707.5 U708.3 U708.5 U709.3 U709.5 | length 105.3
  Copper Layer 3 w0.5: v2(11.75,122.75) v2(71.75,122.75) 73,122.75 v2(75,124.75)
  Bottom Copper w0.25: C751.2@8,122.25 8.115,122.135 11.135,122.135 v2(11.75,122.75) 12.405,123.405 U709.5@14.725,123.405 ; C750.2@23,122.25 23.115,122.135 26.135,122.135 v2(26.75,122.75) 27.405,123.405 U708.5@29.725,123.405 ; C749.2@38,122.25 38.115,122.135 41.135,122.135 v2(41.75,122.75) 42.405,123.405 U707.5@44.725,123.405 ; C748.2@53,122.25 53.115,122.135 56.135,122.135 v2(56.75,122.75) 57.405,123.405 U706.5@59.725,123.405 ; C747.2@68,122.25 68.115,122.135 71.135,122.135 v2(71.75,122.75) 72.405,123.405 U705.5@74.725,123.405 ; v2(75,124.75) C716.2@76.3,124.75 76.3,125.95 R743.1@76.25,126 R741.2@75.25,126 ; C715.2@76.3,123.5 76.3,124.55 C716.2@76.4,124.65
pads on no net: FID1.1 FID2.1 FID3.1 FID4.1 FID5.1 FID6.1 FID7.1 FID8.1 FID9.1 I2S-IN.16 I2S-IN.18 I2S-IN.20 I2S-OUT.1 I2S-OUT.2 I2S-OUT.4 I2S-OUT.5 I2S-OUT.6 I2S-OUT.8 I2S-OUT.9 I2S-OUT.12 I2S-OUT.14 I2S-OUT.15 I2S-OUT.18 I2S-OUT.19 J2.10 J700.10 JTAG.1 JTAG.6 U1.8 U1.9 U1.10 U1.11 U2.4 U2.5 U2.21 U2.24 U2.25 U2.26 U2.29 U2.30 U2.31 U2.32 U2.33 U2.34 U2.35 U2.36 U2.38 U2.39 U2.41 U2.42 U2.43 U2.44 U3.14 U3.15 U3.16 U3.17 U3.25@231.93,19.43 U3.25@231.93,20.57 U3.25@233.07,19.43 U3.25@233.07,20.57 U100.16 U100.19 U100.20 U100.21 U100.25 U100.29 U100.30 U101.45@30,35 U200.16 U200.19 U200.20 U200.21 U200.25 U200.29 U200.30 U201.45@90,35 U300.16 U300.19 U300.20 U300.21 U300.25 U300.29 U300.30 U301.45@150,35 U400.16 U400.19 U400.20 U400.21 U400.25 U400.29 U400.30 U401.45@270,35 U500.16 U500.19 U500.20 U500.21 U500.25 U500.29 U500.30 U501.45@330,35 U600.10 U600.11 U600.16 U600.19 U600.20 U600.21 U600.25 U600.29 U600.30 USB-I2X.3 USB-I2X.5 USB-I2X.7 USB-I2X.9 USB-I2X.11 USB-I2X.13 USB-I2X.14 USB-I2X.15 USB-I2X.16 VR1.9@382.5,78.75

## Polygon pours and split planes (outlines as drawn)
3.3V-VR6 on Top Copper "3.3V-VR6 Top Copper" (solid, remove dead copper, pour order 597): 370.5,45 370.75,44.75 370.75,44.25 370.75,43.25 369.5,42 366.75,42 366.5,42.25 366.5,44.5 367,45 370.5,45
3.3V-1 on Top Copper "3.3V-1 Top Copper" (solid, remove dead copper, pour order 589): 366,23.25 367,24.25 369.75,24.25 370,24.25 370.25,24 370.25,20.5 370,20.25 367,20.25 366,21.25 366,23.25
3.3V-2 on Top Copper "3.3V-2 Top Copper" (solid, remove dead copper, pour order 585): 373.5,9.75 372,11.25 369.5,11.25 369.25,11 369.25,5.5 369.5,5.25 371,5.25 373.5,7.75
12V-VR3 on Top Copper "12V-VR3 Top Copper" (solid, remove dead copper, pour order 577): 374.75,33.5 372.25,31 370,31 370,29.25 370.25,29 372,29 373.75,27.25 373.75,13.75 377,13.75 377.5,14.25 377.5,15.5 376.25,16.75 376.25,32.75 375.5,33.5
15V on Top Copper "15V Top Copper" (solid, remove dead copper, pour order 555): 394.25,64.5 394.75,65 394.75,68.5 394.25,69 391.75,69 391.25,68.5 391.25,65 391.75,64.5
15V on Top Copper "15V Top Copper" (solid, remove dead copper, pour order 553): 381,69.75 380.5,69.25 380.5,66.25 381.25,65.5 383.75,65.5 384.5,66.25 384.5,69.25 384,69.75
SW-VR1 on Top Copper "SW-VR1 Top Copper" (solid, remove dead copper, pour order 551): 394.75,76.75 390.5,76.75 389,75.25 384.25,75.25 384,75 384,74.5 384.25,74.25 394.25,74.25 394.75,74.75
PVDD on Top Copper "PWR-IN Top Copper" (solid, remove dead copper, pour order 545): 362.5,82.5 373.25,82.5 374,81.75 374,80 372.25,78.25 362.5,78.25 362,78.75 362,82
CENTERTWEETER+ on Top Copper "CenterTweeter+ Top Copper" (solid, remove dead copper, pour order 513): 345.25,63.75 345.25,72 344.5,72.75 342.5,72.75 342.25,73 342.25,82 342.5,82.25 347.5,82.25 348.5,81.25 348.5,63.75 345.25,63.75
CENTERWOOFER+ on Top Copper "CenterWoofer+ Top Copper" (solid, remove dead copper, pour order 512): 325.25,63.75 325.25,72 324.5,72.75 322.5,72.75 322.25,73 322.25,82 322.5,82.25 327.5,82.25 328.5,81.25 328.5,63.75 325.25,63.75
CENTERTWEETER- on Top Copper "CenterTweeter- Top Copper" (solid, remove dead copper, pour order 511): 331.5,63.75 339.25,63.75 339.25,72 337.75,73.5 337.75,82 337.5,82.25 332.5,82.25 332.25,82 332.25,68 331.5,67.25 331.5,63.75
CENTERWOOFER- on Top Copper "CenterWoofer- Top Copper" (solid, remove dead copper, pour order 510): 311.5,63.75 319.25,63.75 319.25,72 317.75,73.5 317.75,82 317.5,82.25 312.5,82.25 312.25,82 312.25,68 311.5,67.25 311.5,63.75
OUT5A on Top Copper "OUT5A Top Copper" (solid, remove dead copper, pour order 509): 348.5,58.75 340.75,58.75 340.75,54.25 341,54 344.5,54 344.75,54.25 344.75,55 345,55.25 348.5,55.25
OUT5B on Top Copper "OUT5B Top Copper" (solid, remove dead copper, pour order 508): 331.5,58.75 334.75,58.75 335.5,58 335.5,54.25 335.25,54 331.75,54 331.5,54.25
OUT5C on Top Copper "OUT5C Top Copper" (solid, remove dead copper, pour order 507): 320.75,58.75 328.5,58.75 328.5,54.25 328.25,54 324.75,54 324.5,54.25 324.5,55 324.25,55.25 320.75,55.25
OUT5D on Top Copper "OUT5D Top Copper" (solid, remove dead copper, pour order 506): 311.5,58.75 314.75,58.75 315.5,58 315.5,54.25 315.25,54 311.75,54 311.5,54.25
OUT5A on Top Copper "OUT5A Top Copper" (solid, remove dead copper, pour order 505): 334.2,38.075 334.35,38.225 334.35,41.35 334.625,41.625 334.625,42.875 334.375,43.125 333.875,43.125 333.5,42.75 333.5,41.375 333.275,41.15 333.275,38.225 333.425,38.075
OUT5B on Top Copper "OUT5B Top Copper" (solid, remove dead copper, pour order 504): 331.175,38.225 331.025,38.075 330.875,38.075 330.75,38.2 330.75,39.9 330.65,40 330.65,42.625 330.875,42.85 331.125,42.85 331.35,42.625 331.35,40.075 331.175,39.9
OUT5C on Top Copper "OUT5C Top Copper" (solid, remove dead copper, pour order 503): 328.825,38.225 328.975,38.075 329.125,38.075 329.25,38.2 329.25,39.9 329.35,40 329.35,42.625 329.125,42.85 328.875,42.85 328.65,42.625 328.65,40.075 328.825,39.9
OUT5D on Top Copper "OUT5D Top Copper" (solid, remove dead copper, pour order 502): 325.8,38.075 325.65,38.225 325.65,41.35 325.375,41.625 325.375,42.875 325.625,43.125 326.125,43.125 326.5,42.75 326.5,41.375 326.725,41.15 326.725,38.225 326.575,38.075
PVDD on Top Copper "PVDD5a Top Copper" (solid, remove dead copper, pour order 501): 23 vertices, not listed, extent 307.5,38.075 328.625,52
PVDD on Top Copper "PVDD5b Top Copper" (solid, remove dead copper, pour order 500): 23 vertices, not listed, extent 331.375,38.075 352.5,52
FRONTLEFTTWEETER+ on Top Copper "FronLeftTweeter+ Top Copper" (solid, remove dead copper, pour order 495): 285.25,63.75 285.25,72 284.5,72.75 282.5,72.75 282.25,73 282.25,82 282.5,82.25 287.5,82.25 288.5,81.25 288.5,63.75 285.25,63.75
FRONTLEFTWOOFER+ on Top Copper "FronLeftWoofer+ Top Copper" (solid, remove dead copper, pour order 494): 265.25,63.75 265.25,72 264.5,72.75 262.5,72.75 262.25,73 262.25,82 262.5,82.25 267.5,82.25 268.5,81.25 268.5,63.75 265.25,63.75
FRONTLEFTTWEETER- on Top Copper "FronLeftTweeter- Top Copper" (solid, remove dead copper, pour order 493): 271.5,63.75 279.25,63.75 279.25,72 277.75,73.5 277.75,82 277.5,82.25 272.5,82.25 272.25,82 272.25,68 271.5,67.25 271.5,63.75
FRONTLEFTWOOFER- on Top Copper "FronLeftWoofer- Top Copper" (solid, remove dead copper, pour order 492): 251.5,63.75 259.25,63.75 259.25,72 257.75,73.5 257.75,82 257.5,82.25 252.5,82.25 252.25,82 252.25,68 251.5,67.25 251.5,63.75
OUT4A on Top Copper "OUT4A Top Copper" (solid, remove dead copper, pour order 491): 288.5,58.75 280.75,58.75 280.75,54.25 281,54 284.5,54 284.75,54.25 284.75,55 285,55.25 288.5,55.25
OUT4B on Top Copper "OUT4B Top Copper" (solid, remove dead copper, pour order 490): 271.5,58.75 274.75,58.75 275.5,58 275.5,54.25 275.25,54 271.75,54 271.5,54.25
OUT4C on Top Copper "OUT4C Top Copper" (solid, remove dead copper, pour order 489): 260.75,58.75 268.5,58.75 268.5,54.25 268.25,54 264.75,54 264.5,54.25 264.5,55 264.25,55.25 260.75,55.25
OUT4D on Top Copper "OUT4D Top Copper" (solid, remove dead copper, pour order 488): 251.5,58.75 254.75,58.75 255.5,58 255.5,54.25 255.25,54 251.75,54 251.5,54.25
OUT4A on Top Copper "OUT4A Top Copper" (solid, remove dead copper, pour order 487): 274.2,38.075 274.35,38.225 274.35,41.35 274.625,41.625 274.625,42.875 274.375,43.125 273.875,43.125 273.5,42.75 273.5,41.375 273.275,41.15 273.275,38.225 273.425,38.075
OUT4B on Top Copper "OUT4B Top Copper" (solid, remove dead copper, pour order 486): 271.175,38.225 271.025,38.075 270.875,38.075 270.75,38.2 270.75,39.9 270.65,40 270.65,42.625 270.875,42.85 271.125,42.85 271.35,42.625 271.35,40.075 271.175,39.9
OUT4C on Top Copper "OUT4C Top Copper" (solid, remove dead copper, pour order 485): 268.825,38.225 268.975,38.075 269.125,38.075 269.25,38.2 269.25,39.9 269.35,40 269.35,42.625 269.125,42.85 268.875,42.85 268.65,42.625 268.65,40.075 268.825,39.9
OUT4D on Top Copper "OUT4D Top Copper" (solid, remove dead copper, pour order 484): 265.8,38.075 265.65,38.225 265.65,41.35 265.375,41.625 265.375,42.875 265.625,43.125 266.125,43.125 266.5,42.75 266.5,41.375 266.725,41.15 266.725,38.225 266.575,38.075
PVDD on Top Copper "PVDD4a Top Copper" (solid, remove dead copper, pour order 483): 23 vertices, not listed, extent 247.5,38.075 268.625,52
PVDD on Top Copper "PVDD4b Top Copper" (solid, remove dead copper, pour order 482): 23 vertices, not listed, extent 271.375,38.075 292.5,52
FRONTRIGHTTWEETER+ on Top Copper "FrontRightTweeter+ Top Copper" (solid, remove dead copper, pour order 481): 165.25,63.75 165.25,72 164.5,72.75 162.5,72.75 162.25,73 162.25,82 162.5,82.25 167.5,82.25 168.5,81.25 168.5,63.75 165.25,63.75
FRONTRIGHTWOOFER+ on Top Copper "FrontRightWoofer+ Top Copper" (solid, remove dead copper, pour order 480): 145.25,63.75 145.25,72 144.5,72.75 142.5,72.75 142.25,73 142.25,82 142.5,82.25 147.5,82.25 148.5,81.25 148.5,63.75 145.25,63.75
FRONTRIGHTTWEETER- on Top Copper "FrontRightTweeter- Top Copper" (solid, remove dead copper, pour order 479): 151.5,63.75 159.25,63.75 159.25,72 157.75,73.5 157.75,82 157.5,82.25 152.5,82.25 152.25,82 152.25,68 151.5,67.25 151.5,63.75
FRONTRIGHTWOOFER- on Top Copper "FrontRightWoofer- Top Copper" (solid, remove dead copper, pour order 478): 131.5,63.75 139.25,63.75 139.25,72 137.75,73.5 137.75,82 137.5,82.25 132.5,82.25 132.25,82 132.25,68 131.5,67.25 131.5,63.75
OUT3A on Top Copper "OUT3A Top Copper" (solid, remove dead copper, pour order 477): 168.5,58.75 160.75,58.75 160.75,54.25 161,54 164.5,54 164.75,54.25 164.75,55 165,55.25 168.5,55.25
OUT3B on Top Copper "OUT3B Top Copper" (solid, remove dead copper, pour order 476): 151.5,58.75 154.75,58.75 155.5,58 155.5,54.25 155.25,54 151.75,54 151.5,54.25
OUT3C on Top Copper "OUT3C Top Copper" (solid, remove dead copper, pour order 475): 140.75,58.75 148.5,58.75 148.5,54.25 148.25,54 144.75,54 144.5,54.25 144.5,55 144.25,55.25 140.75,55.25
OUT3D on Top Copper "OUT3D Top Copper" (solid, remove dead copper, pour order 474): 131.5,58.75 134.75,58.75 135.5,58 135.5,54.25 135.25,54 131.75,54 131.5,54.25
OUT3A on Top Copper "OUT3A Top Copper" (solid, remove dead copper, pour order 473): 154.2,38.075 154.35,38.225 154.35,41.35 154.625,41.625 154.625,42.875 154.375,43.125 153.875,43.125 153.5,42.75 153.5,41.375 153.275,41.15 153.275,38.225 153.425,38.075
OUT3B on Top Copper "OUT3B Top Copper" (solid, remove dead copper, pour order 472): 151.175,38.225 151.025,38.075 150.875,38.075 150.75,38.2 150.75,39.9 150.65,40 150.65,42.625 150.875,42.85 151.125,42.85 151.35,42.625 151.35,40.075 151.175,39.9
OUT3C on Top Copper "OUT3C Top Copper" (solid, remove dead copper, pour order 471): 148.825,38.225 148.975,38.075 149.125,38.075 149.25,38.2 149.25,39.9 149.35,40 149.35,42.625 149.125,42.85 148.875,42.85 148.65,42.625 148.65,40.075 148.825,39.9
OUT3D on Top Copper "OUT3D Top Copper" (solid, remove dead copper, pour order 470): 145.8,38.075 145.65,38.225 145.65,41.35 145.375,41.625 145.375,42.875 145.625,43.125 146.125,43.125 146.5,42.75 146.5,41.375 146.725,41.15 146.725,38.225 146.575,38.075
PVDD on Top Copper "PVDD3a Top Copper" (solid, remove dead copper, pour order 469): 23 vertices, not listed, extent 127.5,38.075 148.625,52
PVDD on Top Copper "PVDD3b Top Copper" (solid, remove dead copper, pour order 468): 23 vertices, not listed, extent 151.375,38.075 172.5,52
UPL+ on Top Copper "UpL+ Top Copper" (solid, remove dead copper, pour order 467): 105.25,63.75 105.25,72 104.5,72.75 102.5,72.75 102.25,73 102.25,82 102.5,82.25 107.5,82.25 108.5,81.25 108.5,63.75 105.25,63.75
UPR+ on Top Copper "UpR+ Top Copper" (solid, remove dead copper, pour order 466): 85.25,63.75 85.25,72 84.5,72.75 82.5,72.75 82.25,73 82.25,82 82.5,82.25 87.5,82.25 88.5,81.25 88.5,63.75 85.25,63.75
UPL- on Top Copper "UpL- Top Copper" (solid, remove dead copper, pour order 465): 91.5,63.75 99.25,63.75 99.25,72 97.75,73.5 97.75,82 97.5,82.25 92.5,82.25 92.25,82 92.25,68 91.5,67.25 91.5,63.75
UPR- on Top Copper "UpR- Top Copper" (solid, remove dead copper, pour order 464): 71.5,63.75 79.25,63.75 79.25,72 77.75,73.5 77.75,82 77.5,82.25 72.5,82.25 72.25,82 72.25,68 71.5,67.25 71.5,63.75
OUT2A on Top Copper "OUT2A Top Copper" (solid, remove dead copper, pour order 463): 108.5,58.75 100.75,58.75 100.75,54.25 101,54 104.5,54 104.75,54.25 104.75,55 105,55.25 108.5,55.25
OUT2B on Top Copper "OUT2B Top Copper" (solid, remove dead copper, pour order 462): 91.5,58.75 94.75,58.75 95.5,58 95.5,54.25 95.25,54 91.75,54 91.5,54.25
OUT2C on Top Copper "OUT2C Top Copper" (solid, remove dead copper, pour order 461): 80.75,58.75 88.5,58.75 88.5,54.25 88.25,54 84.75,54 84.5,54.25 84.5,55 84.25,55.25 80.75,55.25
OUT2D on Top Copper "OUT2D Top Copper" (solid, remove dead copper, pour order 460): 71.5,58.75 74.75,58.75 75.5,58 75.5,54.25 75.25,54 71.75,54 71.5,54.25
OUT2A on Top Copper "OUT2A Top Copper" (solid, remove dead copper, pour order 459): 94.2,38.075 94.35,38.225 94.35,41.35 94.625,41.625 94.625,42.875 94.375,43.125 93.875,43.125 93.5,42.75 93.5,41.375 93.275,41.15 93.275,38.225 93.425,38.075
OUT2B on Top Copper "OUT2B Top Copper" (solid, remove dead copper, pour order 458): 91.175,38.225 91.025,38.075 90.875,38.075 90.75,38.2 90.75,39.9 90.65,40 90.65,42.625 90.875,42.85 91.125,42.85 91.35,42.625 91.35,40.075 91.175,39.9
OUT2C on Top Copper "OUT2C Top Copper" (solid, remove dead copper, pour order 457): 88.825,38.225 88.975,38.075 89.125,38.075 89.25,38.2 89.25,39.9 89.35,40 89.35,42.625 89.125,42.85 88.875,42.85 88.65,42.625 88.65,40.075 88.825,39.9
OUT2D on Top Copper "OUT2D Top Copper" (solid, remove dead copper, pour order 456): 85.8,38.075 85.65,38.225 85.65,41.35 85.375,41.625 85.375,42.875 85.625,43.125 86.125,43.125 86.5,42.75 86.5,41.375 86.725,41.15 86.725,38.225 86.575,38.075
PVDD on Top Copper "PVDD2a Top Copper" (solid, remove dead copper, pour order 455): 23 vertices, not listed, extent 67.5,38.075 88.625,52
PVDD on Top Copper "PVDD2b Top Copper" (solid, remove dead copper, pour order 454): 23 vertices, not listed, extent 91.375,38.075 112.5,52
SURROUNDLEFT+ on Top Copper "SurroundL+ Top Copper" (solid, remove dead copper, pour order 449): 45.25,63.75 45.25,72 44.5,72.75 42.5,72.75 42.25,73 42.25,82 42.5,82.25 47.5,82.25 48.5,81.25 48.5,63.75 45.25,63.75
SURROUNDRIGHT+ on Top Copper "SurroundR+ Top Copper" (solid, remove dead copper, pour order 448): 25.25,63.75 25.25,72 24.5,72.75 22.5,72.75 22.25,73 22.25,82 22.5,82.25 27.5,82.25 28.5,81.25 28.5,63.75 25.25,63.75
SURROUNDLEFT- on Top Copper "SurroundL- Top Copper" (solid, remove dead copper, pour order 447): 31.5,63.75 39.25,63.75 39.25,72 37.75,73.5 37.75,82 37.5,82.25 32.5,82.25 32.25,82 32.25,68 31.5,67.25 31.5,63.75
SURROUNDRIGHT- on Top Copper "SurroundR- Top Copper" (solid, remove dead copper, pour order 446): 11.5,63.75 19.25,63.75 19.25,72 17.75,73.5 17.75,82 17.5,82.25 12.5,82.25 12.25,82 12.25,68 11.5,67.25 11.5,63.75
OUT1A on Top Copper "OUT1A Top Copper" (solid, remove dead copper, pour order 445): 48.5,58.75 40.75,58.75 40.75,54.25 41,54 44.5,54 44.75,54.25 44.75,55 45,55.25 48.5,55.25
OUT1B on Top Copper "OUT1B Top Copper" (solid, remove dead copper, pour order 444): 31.5,58.75 34.75,58.75 35.5,58 35.5,54.25 35.25,54 31.75,54 31.5,54.25
OUT1C on Top Copper "OUT1C Top Copper" (solid, remove dead copper, pour order 443): 20.75,58.75 28.5,58.75 28.5,54.25 28.25,54 24.75,54 24.5,54.25 24.5,55 24.25,55.25 20.75,55.25
OUT1D on Top Copper "OUT1D Top Copper" (solid, remove dead copper, pour order 442): 11.5,58.75 14.75,58.75 15.5,58 15.5,54.25 15.25,54 11.75,54 11.5,54.25
OUT1A on Top Copper "OUT1A Top Copper" (solid, remove dead copper, pour order 440): 34.2,38.075 34.35,38.225 34.35,41.35 34.625,41.625 34.625,42.875 34.375,43.125 33.875,43.125 33.5,42.75 33.5,41.375 33.275,41.15 33.275,38.225 33.425,38.075
OUT1B on Top Copper "OUT1B Top Copper" (solid, remove dead copper, pour order 439): 31.175,38.225 31.025,38.075 30.875,38.075 30.75,38.2 30.75,39.9 30.65,40 30.65,42.625 30.875,42.85 31.125,42.85 31.35,42.625 31.35,40.075 31.175,39.9
OUT1C on Top Copper "OUT1C Top Copper" (solid, remove dead copper, pour order 438): 28.825,38.225 28.975,38.075 29.125,38.075 29.25,38.2 29.25,39.9 29.35,40 29.35,42.625 29.125,42.85 28.875,42.85 28.65,42.625 28.65,40.075 28.825,39.9
OUT1D on Top Copper "OUT1D Top Copper" (solid, remove dead copper, pour order 437): 25.8,38.075 25.65,38.225 25.65,41.35 25.375,41.625 25.375,42.875 25.625,43.125 26.125,43.125 26.5,42.75 26.5,41.375 26.725,41.15 26.725,38.225 26.575,38.075
PVDD on Top Copper "PVDD1a Top Copper" (solid, remove dead copper, pour order 436): 23 vertices, not listed, extent 7.5,38.075 28.625,52
PVDD on Top Copper "PVDD1b Top Copper" (solid, remove dead copper, pour order 441): 23 vertices, not listed, extent 31.375,38.075 52.5,52
GND-IO on Top Copper "GND-IO Top Copper" (solid, remove dead copper, pour order 541): 5,86 1,90 1,130 5,134 75,134 79.5,129.5 79.5,90 75.5,86
15V on Top Copper "15V Top Copper" (solid, remove dead copper, pour order 569): 371,59 368.25,59 367.75,59.5 367.75,63.25 369.75,63.25 371,62 371,59
15V on Top Copper "15V Top Copper" (solid, remove dead copper, pour order 571): 376,36.5 373.25,36.5 372.75,37 372.75,40.75 374.75,40.75 376,39.5 376,36.5
12V-VR2 on Top Copper "12V-VR2 Top Copper" (solid, remove dead copper, pour order 575): 370.75,56 369.5,56 367.5,54 367.5,49 370.5,46 374,46 374,52.75 370.75,56
GND on Top Copper "GND Top Copper" (solid, remove dead copper, pour order 611): 21 vertices, not listed, extent 0.5,0.5 399.5,84.5
12V-VR2 on Bottom Copper "12V-VR2 Bottom Copper" (solid, remove dead copper, pour order 607): 367,54 370.5,54 371,54.5 371,55.5 370.5,56 367,56
3.3V-VR6 on Bottom Copper "3.3V-VR6 Bottom Copper" (solid, remove dead copper, pour order 595): 372,43.75 372,37.25 370,37.25 367.5,34.75 366.25,34.75 365.5,35.5 365.5,43.5 367,45 370.75,45
12V-VR2 on Bottom Copper "12V-VR2 Bottom Copper" (solid, remove dead copper, pour order 593): 370.75,45.75 370,46.5 370,48.75 371,49.75 371.75,49.75 372.25,49.25 372.25,46 372,45.75
3.3V-1 on Bottom Copper "3.3V-1 Bottom Copper" (solid, remove dead copper, pour order 587): 376,25.5 368.25,25.5 366,23.25 366,21.25 368.25,19 376,19 376,25.5
3.3V-2 on Bottom Copper "3.3V-2 Bottom Copper" (solid, remove dead copper, pour order 583): 376,11.25 369.75,11.25 369.25,10.75 369.25,5.5 370,4.75 376,4.75 376.25,5 376.25,11
12V-VR3 on Bottom Copper "12V-VR3 Top Copper" (solid, remove dead copper, pour order 581): 373.75,16.5 373.75,14.5 375,13.25 376.5,13.25 377.5,14.25 377.5,15.75 376,17.25 374.5,17.25
12V-VR3 on Bottom Copper "12V-VR3 Top Copper" (solid, remove dead copper, pour order 579): 374.5,33.5 372.75,31.75 372.75,28.5 373.75,27.5 376.25,27.5 376.25,32.75 375.5,33.5 374.5,33.5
